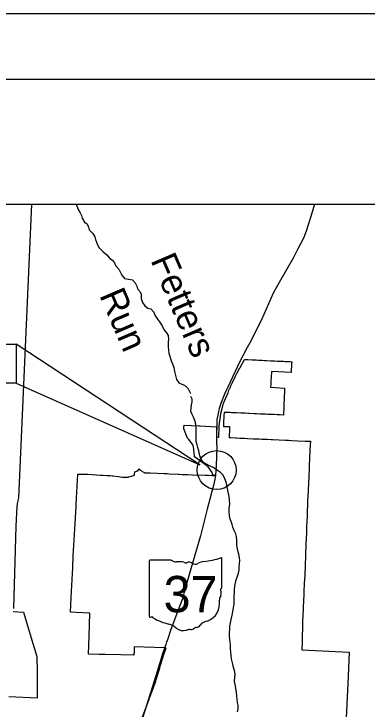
# Model space of a CAD drawing. Extents: x 0 to 34, y 0 to 22.
# Drawn here: x 9.62 to 12.32, y 16.68 to 22 of the extents above; entities that cross this region are included whole.
import ezdxf

# ---------------------------------------------------------------- set-up
doc = ezdxf.new("R2010")
doc.units = 0
for name, color, linetype in [('BR_P_Gen_Text', 7, 'Continuous'), ('Default', 7, 'Continuous'), ('GM_X_Corporation', 7, 'Continuous'), ('GM_X_Minor_River', 7, 'Continuous'), ('GM_X_Minor_River_Text', 7, 'Continuous'), ('GM_X_State_Location', 7, 'Continuous'), ('GM_X_State_Route', 7, 'Continuous'), ('GM_X_State_Shield', 7, 'Continuous'), ('GM_X_Township', 7, 'Continuous'), ('SH_Border', 7, 'Continuous'), ('SH_Cut_Line', 7, 'Continuous'), ('SH_Text', 7, 'Continuous')]:
    doc.layers.add(name, color=color, linetype=linetype)

msp = doc.modelspace()

# ---------------------------------------------------------------- linework, layer by layer
at = {"layer": 'BR_P_Gen_Text'}
for points in [[(8.2347, 19.4714), (9.6343, 19.4714), (9.6343, 19.1712), (8.2347, 19.1712)], [(9.6343, 19.4714), (9.6343, 19.1712), (11.0416, 18.5461)]]:
    msp.add_lwpolyline(points, close=True, dxfattribs=at)
at = {"layer": 'Default'}
msp.add_circle((11.17, 18.5069), 0.149, dxfattribs=at)
at = {"layer": 'GM_X_Corporation'}
for points in [[(10.5643, 16.5156), (10.6425, 16.7245), (10.653, 16.7524), (10.6536, 16.754), (10.6948, 16.8616), (10.696, 16.8653), (10.6963, 16.8666), (10.7076, 16.9035), (10.7312, 16.9812), (10.734, 16.9903), (10.7384, 17.0049), (10.7605, 17.0775), (10.7612, 17.0796), (10.7689, 17.1031), (10.7823, 17.1443), (10.7785, 17.1444), (10.7699, 17.1448), (10.5391, 17.1533), (10.538, 17.1229), (10.5368, 17.0885), (10.5368, 17.0885), (10.4373, 17.0913), (10.3193, 17.0947), (10.2707, 17.096), (10.1881, 17.0984), (10.1932, 17.235), (10.1998, 17.4108), (10.0927, 17.4163), (10.0507, 17.4184), (10.0562, 17.5316), (10.0673, 17.7611), (10.0721, 17.8499), (10.0811, 18.0146), (10.088, 18.1419), (10.0927, 18.2267), (10.0929, 18.2318), (10.0937, 18.2459), (10.1057, 18.4758), (10.1061, 18.4758), (10.1841, 18.4751), (10.2791, 18.4691), (10.2973, 18.468), (10.3284, 18.4662), (10.355, 18.4646), (10.3706, 18.4631), (10.371, 18.4631), (10.3766, 18.4626), (10.4152, 18.458), (10.4472, 18.4536), (10.4593, 18.4523), (10.4597, 18.4522), (10.4601, 18.4522), (10.4605, 18.4522), (10.4609, 18.4521), (10.4613, 18.4521), (10.4617, 18.4521), (10.4621, 18.452), (10.4625, 18.452), (10.4629, 18.452), (10.4633, 18.4519), (10.4637, 18.4519), (10.4641, 18.4519), (10.4645, 18.4519), (10.4649, 18.4518), (10.4653, 18.4518), (10.4657, 18.4518), (10.4661, 18.4518), (10.4665, 18.4518), (10.4669, 18.4517), (10.4673, 18.4517), (10.4677, 18.4517), (10.4681, 18.4517), (10.4685, 18.4517), (10.4689, 18.4517), (10.4693, 18.4517), (10.4697, 18.4517), (10.4701, 18.4517), (10.4705, 18.4517), (10.4709, 18.4517), (10.4713, 18.4517), (10.4717, 18.4517), (10.4721, 18.4517), (10.4725, 18.4517), (10.4729, 18.4517), (10.4733, 18.4517), (10.4737, 18.4517), (10.4741, 18.4517), (10.4745, 18.4517), (10.4749, 18.4517), (10.4753, 18.4518), (10.4757, 18.4518), (10.4761, 18.4518), (10.4765, 18.4518), (10.4769, 18.4518), (10.4772, 18.4519), (10.4776, 18.4519), (10.478, 18.4519), (10.4784, 18.4519), (10.4788, 18.452), (10.4792, 18.452), (10.4796, 18.452), (10.48, 18.4521), (10.4804, 18.4521), (10.4808, 18.4521), (10.4812, 18.4522), (10.4816, 18.4522), (10.482, 18.4522), (10.4824, 18.4523), (10.4828, 18.4523), (10.4832, 18.4524), (10.4836, 18.4524), (10.484, 18.4525), (10.4844, 18.4525), (10.4848, 18.4526), (10.4852, 18.4526), (10.4856, 18.4527), (10.486, 18.4527), (10.4864, 18.4528), (10.4868, 18.4528), (10.4871, 18.4529), (10.4875, 18.453), (10.4879, 18.453), (10.4883, 18.4531), (10.4887, 18.4531), (10.4891, 18.4532), (10.4895, 18.4533), (10.4899, 18.4533), (10.4903, 18.4534), (10.4907, 18.4535), (10.4911, 18.4536), (10.4915, 18.4536), (10.4919, 18.4537), (10.4923, 18.4538), (10.4927, 18.4539), (10.493, 18.4539), (10.4934, 18.454), (10.4938, 18.4541), (10.4942, 18.4542), (10.4946, 18.4543), (10.495, 18.4544), (10.4954, 18.4545), (10.4958, 18.4545), (10.4962, 18.4546), (10.4966, 18.4547), (10.497, 18.4548), (10.4973, 18.4549), (10.4977, 18.455), (10.4981, 18.4551), (10.4989, 18.4553), (10.5185, 18.4613), (10.5412, 18.4683), (10.5414, 18.4718), (10.5429, 18.4938), (10.5519, 18.4965), (10.5614, 18.5002), (10.5618, 18.5003), (10.5621, 18.5005), (10.5625, 18.5007), (10.5628, 18.5009), (10.5632, 18.5011), (10.5635, 18.5013), (10.5639, 18.5015), (10.5642, 18.5017), (10.5645, 18.502), (10.5649, 18.5022), (10.5652, 18.5024), (10.5655, 18.5027), (10.5658, 18.5029), (10.5661, 18.5032), (10.5664, 18.5034), (10.5667, 18.5037), (10.567, 18.504), (10.5673, 18.5042), (10.5676, 18.5045), (10.5679, 18.5048), (10.5681, 18.5051), (10.5684, 18.5054), (10.5687, 18.5057), (10.5689, 18.506), (10.5692, 18.5063), (10.5694, 18.5066), (10.5697, 18.5069), (10.5699, 18.5072), (10.5702, 18.5075), (10.5704, 18.5079), (10.5706, 18.5082), (10.5708, 18.5085), (10.5711, 18.5089), (10.5713, 18.5092), (10.5715, 18.5096), (10.5717, 18.5099), (10.5719, 18.5103), (10.572, 18.5106), (10.5722, 18.511), (10.5724, 18.5113), (10.5726, 18.5117), (10.5727, 18.5121), (10.5729, 18.5124), (10.573, 18.5128), (10.5731, 18.5132), (10.5733, 18.5136), (10.5734, 18.5139), (10.5735, 18.5143), (10.5736, 18.5147), (10.5737, 18.5151), (10.5739, 18.5158), (10.5829, 18.5094), (10.5847, 18.5081), (10.5898, 18.5045), (10.5944, 18.5012), (10.6007, 18.4968), (10.6111, 18.4897), (10.6119, 18.4893), (10.6123, 18.4891), (10.6127, 18.489), (10.613, 18.4888), (10.6133, 18.4887), (10.6134, 18.4887), (10.6135, 18.4886), (10.6138, 18.4885), (10.6142, 18.4884), (10.6145, 18.4883), (10.6149, 18.4881), (10.6153, 18.488), (10.6157, 18.4879), (10.6161, 18.4878), (10.6165, 18.4877), (10.6168, 18.4876), (10.6172, 18.4875), (10.6176, 18.4874), (10.618, 18.4873), (10.6184, 18.4872), (10.6188, 18.4872), (10.6192, 18.4871), (10.6196, 18.4871), (10.62, 18.487), (10.6204, 18.4869), (10.6208, 18.4869), (10.6212, 18.4869), (10.6216, 18.4868), (10.622, 18.4868), (10.6303, 18.4861), (10.6596, 18.4847), (10.7667, 18.4805), (10.7906, 18.4795), (10.791, 18.4795), (10.8061, 18.4789), (10.8752, 18.4757), (10.8756, 18.4757), (10.8824, 18.4753), (10.8828, 18.4753), (10.9089, 18.4741), (10.9094, 18.4741), (10.9371, 18.4728), (10.9473, 18.4725), (10.9477, 18.4725), (10.9855, 18.4713), (10.986, 18.4712), (11.0809, 18.4682), (11.1067, 18.4674), (11.134, 18.4664), (11.1553, 18.466), (11.1555, 18.4666), (11.139, 18.4736), (11.1384, 18.4772), (11.1367, 18.4879), (11.105, 18.5309), (11.0254, 18.5899), (11.0007, 18.6083), (10.9995, 18.62), (10.9982, 18.6321), (10.9953, 18.661), (10.993, 18.6845), (10.9866, 18.7009), (10.9836, 18.7089), (10.9562, 18.7398), (10.9461, 18.7513), (10.9191, 18.8236), (10.9194, 18.8331), (10.92, 18.8509), (11.0346, 18.8451), (11.0374, 18.8449), (11.0432, 18.8447), (11.1694, 18.8381), (11.1689, 18.8054), (11.1683, 18.7603), (11.1803, 18.7597), (11.1867, 18.7594), (11.1886, 18.8433), (11.1919, 18.8673), (11.2033, 18.9499), (11.2194, 19.0092), (11.2233, 19.0181), (11.2514, 19.0828), (11.2552, 19.0916), (11.2579, 19.0996), (11.2644, 19.119), (11.2684, 19.1279), (11.2706, 19.1327), (11.2755, 19.1435), (11.2795, 19.1523), (11.2891, 19.1733), (11.3012, 19.2001), (11.3029, 19.2039), (11.3141, 19.225), (11.3283, 19.252), (11.3487, 19.2906), (11.3494, 19.2903), (11.3503, 19.2919), (11.3832, 19.3543), (11.4095, 19.353), (11.4424, 19.3514), (11.4716, 19.35), (11.4894, 19.3491), (11.491, 19.349), (11.4942, 19.3489), (11.5189, 19.3477), (11.5372, 19.3468), (11.5425, 19.3465), (11.5442, 19.3464), (11.5506, 19.3461), (11.5851, 19.3444), (11.613, 19.343), (11.633, 19.3421), (11.6809, 19.3397), (11.6946, 19.339), (11.7288, 19.3374), (11.7333, 19.3371), (11.7449, 19.3366), (11.7441, 19.319), (11.7433, 19.3046), (11.7418, 19.273), (11.7409, 19.2549), (11.589, 19.2623), (11.5868, 19.2151), (11.5857, 19.1906), (11.5851, 19.1787), (11.5843, 19.1619), (11.5834, 19.1406), (11.6907, 19.1354), (11.6901, 19.1211), (11.6894, 19.1054), (11.6877, 19.0685), (11.6867, 19.046), (11.6857, 19.0223), (11.6843, 18.9917), (11.6815, 18.9283), (11.6576, 18.9294), (11.6337, 18.9304), (11.6097, 18.9315), (11.5854, 18.9326), (11.5618, 18.9337), (11.5447, 18.9345), (11.5239, 18.9354), (11.5193, 18.9356), (11.5159, 18.9358), (11.504, 18.9363), (11.4764, 18.9376), (11.4661, 18.9381), (11.4566, 18.9385), (11.4182, 18.9402), (11.4142, 18.9404), (11.3848, 18.9417), (11.3703, 18.9424), (11.3668, 18.9426), (11.3561, 18.943), (11.3224, 18.9446), (11.2828, 18.9463), (11.2745, 18.9467), (11.2662, 18.9471), (11.2266, 18.9489), (11.2252, 18.9213), (11.2225, 18.8658), (11.2215, 18.8418), (11.2694, 18.8396), (11.2686, 18.8218), (11.2657, 18.7558), (11.2657, 18.7558), (11.2793, 18.7552), (11.3136, 18.7536), (11.3176, 18.7534), (11.322, 18.7532), (11.348, 18.752), (11.3615, 18.7514), (11.3647, 18.7513), (11.3834, 18.7504), (11.4074, 18.7493), (11.4092, 18.7492), (11.4093, 18.7492), (11.4501, 18.7473), (11.4551, 18.7471), (11.4572, 18.747), (11.4928, 18.7454), (11.4939, 18.7453), (11.4951, 18.7453), (11.5151, 18.7444), (11.553, 18.7426), (11.5558, 18.7425), (11.5882, 18.741), (11.5965, 18.7406), (11.5969, 18.7406), (11.6009, 18.7404), (11.6488, 18.7382), (11.6967, 18.736), (11.7201, 18.7349), (11.7446, 18.7338), (11.7925, 18.7316), (11.8489, 18.729), (11.8879, 18.7272), (11.8877, 18.7231), (11.8868, 18.7018), (11.8823, 18.604), (11.8791, 18.5358), (11.8774, 18.4979), (11.8764, 18.4771), (11.875, 18.4457), (11.8737, 18.4181), (11.8729, 18.4011), (11.871, 18.3592), (11.8699, 18.3346), (11.869, 18.3169), (11.8689, 18.3134), (11.8669, 18.2699), (11.8663, 18.2569), (11.8653, 18.2359), (11.8638, 18.195), (11.8631, 18.1778), (11.8622, 18.154), (11.8622, 18.154), (11.8606, 18.1129), (11.859, 18.0719), (11.8584, 18.055), (11.8574, 18.0307), (11.857, 18.0211), (11.8557, 17.9876), (11.8539, 17.9397), (11.8507, 17.8561), (11.8475, 17.7748), (11.8444, 17.7056), (11.8442, 17.7007), (11.8414, 17.6408), (11.8412, 17.6362), (11.8387, 17.5809), (11.8368, 17.5392), (11.836, 17.5211), (11.8349, 17.497), (11.8333, 17.4612), (11.8321, 17.4342), (11.8306, 17.4013), (11.8279, 17.3417), (11.8239, 17.1929), (11.8223, 17.1309), (12.1855, 17.1127), (12.1771, 16.9272), (12.1604, 16.5563)], [(9.612, 17.4228), (9.6479, 17.4213), (9.6898, 17.4196), (9.7471, 17.2291), (9.7931, 17.0786), (9.794, 16.9615), (9.7944, 16.9011), (9.794, 16.7606), (9.579, 16.7702)]]:
    msp.add_lwpolyline(points, dxfattribs=at)
at = {"layer": 'GM_X_Minor_River'}
for points in [[(10.0908, 20.5443), (10.1006, 20.5246), (10.1102, 20.5022), (10.1222, 20.4821), (10.1342, 20.4557), (10.139, 20.4349), (10.1583, 20.406), (10.1783, 20.3924), (10.1887, 20.3667), (10.1927, 20.3467), (10.2224, 20.3194), (10.2376, 20.2938), (10.2424, 20.2737), (10.2504, 20.2521), (10.2584, 20.232), (10.2704, 20.2088), (10.3001, 20.1791), (10.3281, 20.1559), (10.3506, 20.127), (10.3722, 20.1134), (10.3867, 20.0933), (10.3963, 20.0725), (10.4211, 20.046), (10.4315, 20.026), (10.4443, 20.0003), (10.4636, 19.9739), (10.4957, 19.9698), (10.5245, 19.9642), (10.5462, 19.9418), (10.5582, 19.9153), (10.563, 19.8953), (10.5854, 19.8728), (10.5918, 19.8528), (10.591, 19.8207), (10.603, 19.7895), (10.6199, 19.7638)], [(10.6199, 19.7638), (10.6423, 19.7462), (10.6656, 19.7406), (10.6888, 19.7149), (10.696, 19.6933), (10.7176, 19.6636), (10.7321, 19.6427), (10.7521, 19.6123), (10.7665, 19.5842), (10.7866, 19.557), (10.7994, 19.5369), (10.8018, 19.5097), (10.7985, 19.4873), (10.7985, 19.448), (10.8001, 19.4264), (10.8049, 19.4031), (10.8121, 19.3783), (10.8225, 19.3446), (10.8321, 19.3214), (10.8409, 19.2917), (10.8473, 19.2613), (10.8553, 19.2316), (10.8625, 19.2003), (10.8793, 19.1755), (10.9042, 19.1651), (10.9242, 19.1562), (10.9499, 19.1338), (10.9691, 19.0921)], [(11.3297, 16.6557), (11.3337, 16.6789), (11.3337, 16.7061), (11.3297, 16.7261), (11.3273, 16.7517), (11.3257, 16.7789), (11.3225, 16.8045), (11.3177, 16.8373), (11.3121, 16.8644), (11.3073, 16.8892), (11.3097, 16.9204), (11.3129, 16.9436), (11.3065, 16.9716), (11.2993, 16.9964), (11.2929, 17.0196), (11.2881, 17.042), (11.2841, 17.0627), (11.2801, 17.0859), (11.2777, 17.1131), (11.2761, 17.1403), (11.2753, 17.1651), (11.2729, 17.1923), (11.2705, 17.2123), (11.2681, 17.2355), (11.2681, 17.2611), (11.2705, 17.2867), (11.2721, 17.3091), (11.2761, 17.3363), (11.2816, 17.3635), (11.288, 17.3962), (11.2936, 17.425), (11.2991, 17.4514), (11.3031, 17.4818), (11.3047, 17.5042), (11.3047, 17.5442), (11.3055, 17.5642), (11.307, 17.5946), (11.3086, 17.617), (11.3198, 17.6674), (11.3269, 17.6874), (11.3365, 17.7186), (11.3413, 17.7426), (11.3429, 17.7626), (11.3452, 17.789), (11.3476, 17.8146), (11.3452, 17.8362), (11.3396, 17.8626), (11.3324, 17.8921), (11.3277, 17.9161), (11.3237, 17.9401), (11.3236, 17.9705), (11.3212, 17.9977), (11.3165, 18.0185), (11.3053, 18.0449), (11.2941, 18.0689), (11.2885, 18.0896), (11.2805, 18.112), (11.2718, 18.1392), (11.2678, 18.1624), (11.2662, 18.188), (11.267, 18.2136), (11.2701, 18.2464), (11.2693, 18.2784), (11.2653, 18.3055), (11.2589, 18.3383), (11.2526, 18.3655), (11.247, 18.3911), (11.2422, 18.4135), (11.2326, 18.4399), (11.2198, 18.4678), (11.1999, 18.4886), (11.176, 18.503), (11.1473, 18.5237), (11.121, 18.5373), (11.0923, 18.5517), (11.0683, 18.566), (11.0508, 18.59), (11.0404, 18.6156), (11.0324, 18.6548), (11.0261, 18.6804), (11.0197, 18.7011), (11.0141, 18.7251), (11.0133, 18.7603), (11.0132, 18.8347), (11.01, 18.8579), (11.0037, 18.8875), (10.9917, 18.9123), (10.9813, 18.9322), (10.9733, 18.9546), (10.9749, 18.9834), (10.9781, 19.0066), (10.9813, 19.0306), (10.9813, 19.0506), (10.9733, 19.0706)]]:
    msp.add_lwpolyline(points, dxfattribs=at)
at = {"layer": 'GM_X_State_Route'}
msp.add_line((10.787, 17.1924), (10.7801, 17.1724), dxfattribs=at)
for points in [[(11.9188, 20.5443), (11.8905, 20.4476), (11.8545, 20.3366), (11.835, 20.2829), (11.7897, 20.1951), (11.7556, 20.1296), (11.6489, 19.9435), (11.6036, 19.8619), (11.5144, 19.6568), (11.4232, 19.4815)], [(11.4232, 19.4815), (11.404, 19.4446), (11.3461, 19.3321), (11.255, 19.143), (11.2431, 19.1164)], [(11.2431, 19.1164), (11.2304, 19.0877), (11.2027, 19.0165), (11.19, 18.9781), (11.1875, 18.9671)], [(11.1875, 18.9671), (11.1841, 18.9518), (11.1779, 18.9282), (11.1725, 18.8931), (11.172, 18.8537), (11.1677, 18.7802), (11.1677, 18.7523)], [(11.1677, 18.7523), (11.1677, 18.7164), (11.1705, 18.6813), (11.1668, 18.5407), (11.1622, 18.4677), (11.159, 18.4494), (11.1486, 18.3997), (11.1333, 18.3419), (11.1183, 18.2849)], [(11.1183, 18.2849), (11.0981, 18.2076), (11.0451, 18.0028), (10.9722, 17.7518), (10.9221, 17.5715), (10.9072, 17.5205), (10.8935, 17.4831), (10.82, 17.285), (10.7897, 17.2003), (10.787, 17.1924)], [(10.7801, 17.1724), (10.7574, 17.1066), (10.7147, 16.9653), (10.6654, 16.8089)], [(10.6654, 16.8089), (10.6609, 16.7947), (10.6193, 16.6639), (10.6025, 16.608), (10.5926, 16.5733), (10.5869, 16.548), (10.5794, 16.5132), (10.5702, 16.4695), (10.562, 16.4171), (10.5567, 16.3782), (10.5529, 16.3382)]]:
    msp.add_lwpolyline(points, dxfattribs=at)
at = {"layer": 'GM_X_State_Shield'}
for p, q in [((10.6539, 17.8106), (10.6539, 17.3885)), ((10.8223, 17.8179), (10.6594, 17.8179)), ((11.2101, 17.6075), (11.2101, 17.8283)), ((11.2101, 17.6076), (11.2101, 17.6075))]:
    msp.add_line(p, q, dxfattribs=at)
for centre, radius, start, end in [((11.012, 18.3934), 0.5898, 275.8445, 288.9065), ((11.204, 17.8292), 0.00619, 351.8621, 97.738), ((10.6603, 17.8115), 0.00644, 98.1301, 188.1301), ((10.8611, 17.8669), 0.0625, 231.6195, 271.1119), ((10.8818, 17.5809), 0.2244, 80.4867, 94.9883), ((10.9327, 17.8137), 0.018, 219.7921, 297.1024), ((10.9592, 17.7649), 0.0375, 54.4667, 119.1411), ((11.0076, 17.8318), 0.0451, 233.8562, 294.8282), ((11.0872, 17.6889), 0.1187, 97.3462, 120.7689), ((11.2087, 17.5913), 0.00958, 107.944, 210.337), ((11.1477, 17.5634), 0.0575, 340.033, 23.6496), ((11.2035, 17.6066), 0.00663, 289.6038, 7.7341), ((11.2323, 17.5151), 0.0418, 136.8065, 186.9296), ((11.045, 17.487), 0.1475, 292.3089, 8.9858), ((10.6604, 17.3875), 0.0065, 171.9584, 258.3066), ((10.6614, 17.4307), 0.0496, 267.339, 280.6039), ((10.6715, 17.3641), 0.0179, 29.7484, 93.2717), ((10.8973, 17.7434), 0.4259, 240.4129, 257.1985), ((10.7704, 17.1988), 0.1333, 47.1842, 75.836), ((11.0103, 17.2895), 0.0127, 65.7517, 132.6484), ((11.0049, 17.3476), 0.0477, 282.8732, 323.2771), ((11.1072, 17.27), 0.0808, 94.4031, 142.5768), ((10.9145, 17.362), 0.0846, 230.7004, 286.2918), ((10.9634, 17.2161), 0.0695, 85.6951, 111.2099), ((10.9695, 17.3304), 0.0451, 268.777, 315.5493)]:
    msp.add_arc(centre, radius, start, end, dxfattribs=at)
at = {"layer": 'GM_X_Township'}
msp.add_line((9.7522, 20.5443), (9.6896, 19.1605), dxfattribs=at)
msp.add_lwpolyline([(9.6896, 19.1605), (9.6516, 18.2952), (9.6442, 18.2643), (9.64, 18.2291), (9.6331, 18.0765), (9.6131, 17.4474)], dxfattribs=at)
at = {"layer": 'SH_Border'}
msp.add_lwpolyline([(1.5, 21.5), (33.5, 21.5), (33.5, 0.5), (1.5, 0.5)], close=True, dxfattribs=at)
at = {"layer": 'SH_Cut_Line'}
msp.add_lwpolyline([(0, 0), (34, 0), (34, 22), (0, 22)], close=True, dxfattribs=at)
at = {"layer": 'SH_Text'}
msp.add_lwpolyline([(2.5702, 20.5443), (15.6971, 20.5443), (15.6971, 8.9902), (2.5702, 8.9902)], close=True, dxfattribs=at)

# ---------------------------------------------------------------- texts
at = {"layer": 'GM_X_Minor_River_Text'}
for s, p in [('Fetters', (10.6615, 20.1146)), ('Run', (10.2691, 19.8467))]:
    msp.add_text(s, height=0.19974, rotation=293.2442, dxfattribs=at).set_placement(p)
at = {"layer": 'GM_X_State_Location'}
for s, p in [('s', (10.9258, 17.5715)), ('r', (10.9257, 17.5715))]:
    msp.add_text(s, height=0.0004, dxfattribs=at).set_placement(p)
msp.add_text('37', height=0.0004, rotation=0, dxfattribs=at).set_placement((10.8252, 17.5424))
at = {"layer": 'GM_X_State_Shield'}
msp.add_text('37', height=0.27809, dxfattribs=at).set_placement((10.7636, 17.4182))

doc.saveas('drawing.dxf')
